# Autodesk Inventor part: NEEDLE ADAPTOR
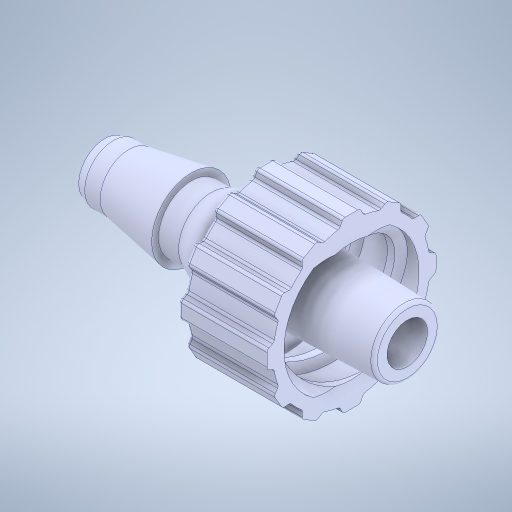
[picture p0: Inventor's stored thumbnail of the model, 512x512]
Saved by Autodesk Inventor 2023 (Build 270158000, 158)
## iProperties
Created: 2025-07
Part Number: NEEDLE ADAPTOR
Material: Generic
Document SubType Name: Modeling
Designer: erjon
Density: 1 g/cm^3
Appearance: Default
Author: erjon
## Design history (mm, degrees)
feature "Base1"
body "Solid1"
